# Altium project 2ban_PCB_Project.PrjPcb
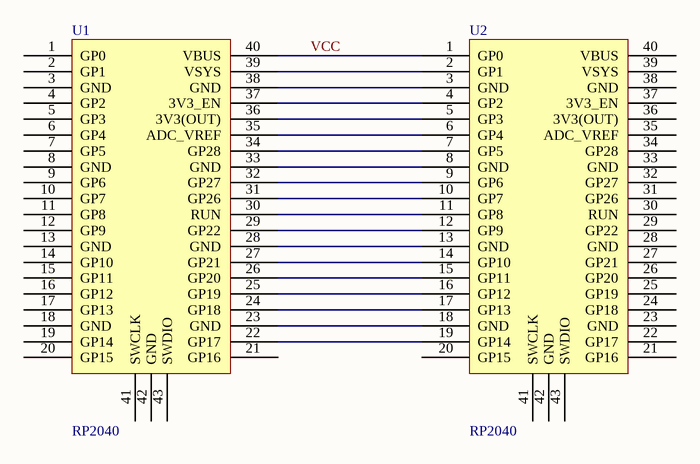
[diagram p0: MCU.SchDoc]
2 sheets, 2 parts. Net scope: global (net labels, ports and power ports of the same name join across sheets).
Board files: PCB1.PcbDoc, PICO_PCB_2ban.PcbDoc
Sheets:
  MCU.SchDoc
  pico_2ban.SchDoc

## Sheet MCU.SchDoc
size A3; SheetNumber: 1; SheetTotal: 2

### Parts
U1  RP2040  [PCBComponent_1]
U2  RP2040  [PCBComponent_1]

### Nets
VCC: U1.40(VBUS) U2.1(GP0)
NetU1_22: U1.22(GP17) U2.19(GP14)
NetU1_23: U1.23(GND) U2.18(GND)
NetU1_24: U1.24(GP18) U2.17(GP13)
NetU1_25: U1.25(GP19) U2.16(GP12)
NetU1_26: U1.26(GP20) U2.15(GP11)
NetU1_27: U1.27(GP21) U2.14(GP10)
NetU1_28: U1.28(GND) U2.13(GND)
NetU1_29: U1.29(GP22) U2.12(GP9)
NetU1_30: U1.30(RUN) U2.11(GP8)
NetU1_31: U1.31(GP26) U2.10(GP7)
NetU1_32: U1.32(GP27) U2.9(GP6)
NetU1_33: U1.33(GND) U2.8(GND)
NetU1_34: U1.34(GP28) U2.7(GP5)
NetU1_35: U1.35(ADC_VREF) U2.6(GP4)
NetU1_36: U1.36(3V3(OUT)) U2.5(GP3)
NetU1_37: U1.37(3V3_EN) U2.4(GP2)
NetU1_38: U1.38(GND) U2.3(GND)
NetU1_39: U1.39(VSYS) U2.2(GP1)

Not connected (* = marked no-connect by the designer): U1 1(GP0) 2(GP1) 3(GND) 4(GP2) 5(GP3) 6(GP4) 7(GP5) 8(GND) 9(GP6) 10(GP7) 11(GP8) 12(GP9) 13(GND) 14(GP10) 15(GP11) 16(GP12) 17(GP13) 18(GND) 19(GP14) 20(GP15) 21(GP16) 41(SWCLK) 42(GND) 43(SWDIO); U2 20(GP15) 21(GP16) 22(GP17) 23(GND) 24(GP18) 25(GP19) 26(GP20) 27(GP21) 28(GND) 29(GP22) 30(RUN) 31(GP26) 32(GP27) 33(GND) 34(GP28) 35(ADC_VREF) 36(3V3(OUT)) 37(3V3_EN) 38(GND) 39(VSYS) 40(VBUS) 41(SWCLK) 42(GND) 43(SWDIO)

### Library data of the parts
U1 U2 = Component_1

## Sheet pico_2ban.SchDoc
size A3; SheetNumber: 1; SheetTotal: 1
